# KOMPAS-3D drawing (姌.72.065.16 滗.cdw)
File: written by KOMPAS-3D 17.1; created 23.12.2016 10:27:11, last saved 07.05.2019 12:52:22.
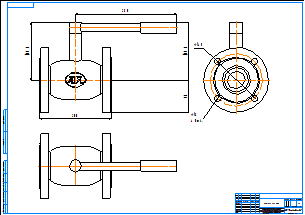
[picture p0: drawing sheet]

Sheet 1: A1, landscape

Title block, sheet 1: name: КШ.72.065.16 фф; material: Внимание! Данный продукт является объектом авторского права ООО «Торговый Дом АДЛ». / Запрещается изменение, копирование, распространение / (в том числе путем копирования на другие сайты и ресурсы в Интернете) / или любое иное использование информации и объектов без предварительного / согласия правообладателя (ООО «Торговый Дом АДЛ»).; sheets: 1; organisation: ООО "Торговый дом АДЛ"; sheet format: A1; stored path: C:\Users\tra\Desktop\2д чертежи\Шаровые краны БИВАЛ\КШ_Бивал_серия_72\KOMPAS_2D\КШ.72.065.16 фф.cdw

Views: Спереди 4, Проекционный вид 5, Проекционный вид 6
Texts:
  Klimkovich
  ADL
Dimensions and other numbers on the sheet: 200; 280; 159,3; 90; 145; 18; 4 Отв.; 1:1; 1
